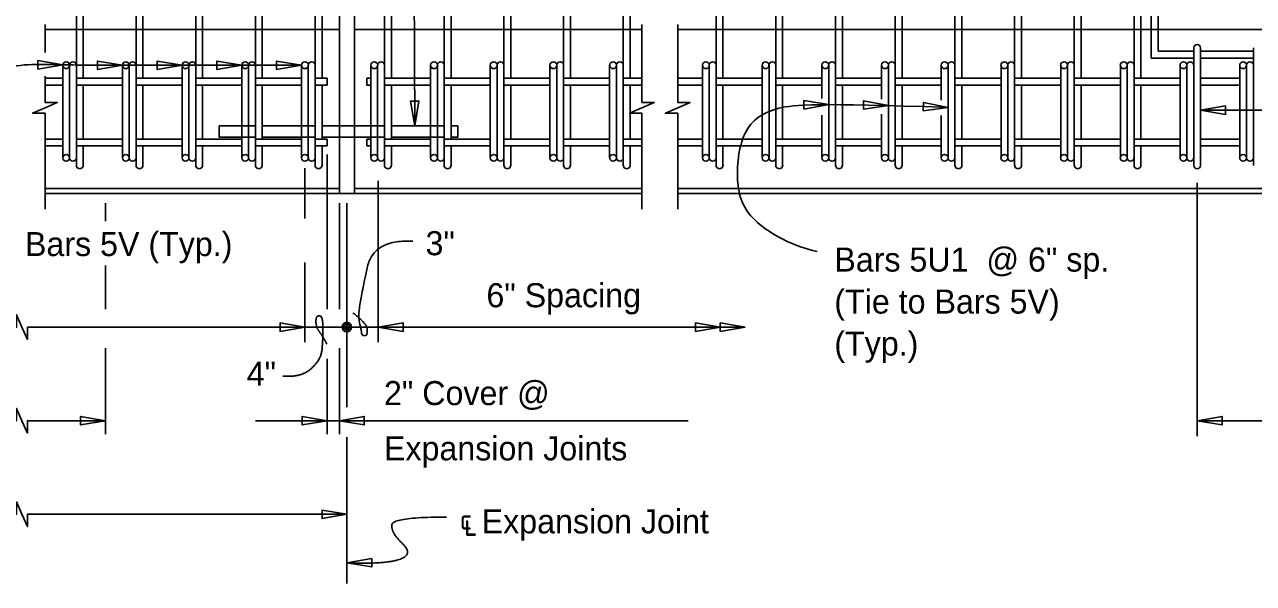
# Model space of a CAD drawing. Extents: x 120577.8 to 120649.9, y 120677.2 to 120721.6.
# Drawn here: x 120592.76 to 120603.05, y 120703.74 to 120708.42 of the extents above; entities that cross this region are included whole.
import ezdxf

# ---------------------------------------------------------------- set-up
doc = ezdxf.new("R2010")
doc.units = 0
for name, color, linetype in [('AdhocPoint_dp', 7, 'Continuous'), ('Border', 7, 'Continuous'), ('Patterning', 7, 'Continuous'), ('PlotBorder_dp', 7, 'Continuous'), ('TextMisc', 7, 'Continuous')]:
    doc.layers.add(name, color=color, linetype=linetype)

msp = doc.modelspace()

# ---------------------------------------------------------------- linework, layer by layer
at = {"layer": 'AdhocPoint_dp'}
msp.add_line((120595.397, 120707.007), (120595.522, 120707.007), dxfattribs=at)
at = {"layer": 'Border'}
for p, q in [((120595.459, 120705.219), (120595.459, 120706.927)), ((120595.459, 120703.741), (120595.459, 120704.966))]:
    msp.add_line(p, q, dxfattribs=at)
at = {"layer": 'Patterning'}
for p, q in [((120593.194, 120707.244), (120593.194, 120713.861)), ((120593.251, 120713.861), (120593.251, 120707.974)), ((120594.194, 120707.244), (120594.194, 120713.861)), ((120594.251, 120713.861), (120594.251, 120707.974)), ((120594.694, 120707.244), (120594.694, 120713.861)), ((120594.751, 120713.861), (120594.751, 120707.974)), ((120595.194, 120707.244), (120595.194, 120713.861)), ((120595.251, 120713.861), (120595.251, 120707.974)), ((120595.774, 120707.244), (120595.774, 120713.861)), ((120595.832, 120713.861), (120595.832, 120707.974)), ((120596.274, 120707.244), (120596.274, 120713.861)), ((120596.332, 120713.861), (120596.332, 120707.974)), ((120596.774, 120707.244), (120596.774, 120713.861)), ((120596.832, 120713.861), (120596.832, 120707.974)), ((120597.274, 120707.244), (120597.274, 120713.861)), ((120597.332, 120713.861), (120597.332, 120707.974)), ((120597.774, 120707.244), (120597.774, 120713.861)), ((120597.832, 120713.861), (120597.832, 120707.974)), ((120598.552, 120707.244), (120598.552, 120713.861)), ((120598.609, 120713.861), (120598.609, 120707.974)), ((120599.052, 120707.244), (120599.052, 120713.861)), ((120599.109, 120713.861), (120599.109, 120707.974)), ((120599.552, 120707.244), (120599.552, 120713.861)), ((120599.609, 120713.861), (120599.609, 120707.974)), ((120600.052, 120707.244), (120600.052, 120713.861)), ((120600.109, 120713.861), (120600.109, 120707.974)), ((120600.552, 120707.244), (120600.552, 120713.861)), ((120600.609, 120713.861), (120600.609, 120707.974)), ((120601.052, 120707.244), (120601.052, 120713.861)), ((120601.109, 120713.861), (120601.109, 120707.974)), ((120601.552, 120707.244), (120601.552, 120713.861)), ((120601.609, 120713.861), (120601.609, 120707.974)), ((120602.052, 120707.244), (120602.052, 120713.861)), ((120602.109, 120713.861), (120602.109, 120707.974)), ((120593.694, 120707.244), (120593.694, 120712.988)), ((120593.751, 120713.013), (120593.751, 120707.974)), ((120602.197, 120708.749), (120602.197, 120708.143)), ((120602.255, 120708.749), (120602.255, 120708.2)), ((120602.255, 120708.2), (120602.552, 120708.2)), ((120602.552, 120707.244), (120602.552, 120708.229)), ((120602.609, 120708.229), (120602.609, 120707.244)), ((120603.052, 120707.244), (120603.052, 120708.229)), ((120593.079, 120708.083), (120593.079, 120707.307)), ((120593.136, 120707.974), (120593.136, 120708.083)), ((120593.136, 120708.083), (120593.136, 120707.387)), ((120593.579, 120708.083), (120593.579, 120707.307)), ((120593.636, 120707.974), (120593.636, 120708.083)), ((120593.636, 120708.083), (120593.636, 120707.387)), ((120594.079, 120708.083), (120594.079, 120707.307)), ((120594.136, 120707.974), (120594.136, 120708.083)), ((120594.136, 120708.083), (120594.136, 120707.387)), ((120594.579, 120708.083), (120594.579, 120707.307)), ((120594.636, 120707.974), (120594.636, 120708.083)), ((120594.636, 120708.083), (120594.636, 120707.387)), ((120595.079, 120708.083), (120595.079, 120707.307)), ((120595.136, 120707.974), (120595.136, 120708.083)), ((120595.136, 120708.083), (120595.136, 120707.387)), ((120595.66, 120708.083), (120595.66, 120707.307)), ((120595.717, 120707.974), (120595.717, 120708.083)), ((120595.717, 120708.083), (120595.717, 120707.387)), ((120596.16, 120708.083), (120596.16, 120707.307)), ((120596.217, 120707.974), (120596.217, 120708.083)), ((120596.217, 120708.083), (120596.217, 120707.387)), ((120596.66, 120708.083), (120596.66, 120707.307)), ((120596.717, 120707.974), (120596.717, 120708.083)), ((120596.717, 120708.083), (120596.717, 120707.387)), ((120597.16, 120708.083), (120597.16, 120707.307)), ((120597.217, 120707.974), (120597.217, 120708.083)), ((120597.217, 120708.083), (120597.217, 120707.387)), ((120597.66, 120708.083), (120597.66, 120707.307)), ((120597.717, 120707.974), (120597.717, 120708.083)), ((120597.717, 120708.083), (120597.717, 120707.387)), ((120598.438, 120708.083), (120598.438, 120707.307)), ((120598.495, 120707.974), (120598.495, 120708.083)), ((120598.495, 120708.083), (120598.495, 120707.387)), ((120598.938, 120708.083), (120598.938, 120707.307)), ((120598.995, 120707.974), (120598.995, 120708.083)), ((120598.995, 120708.083), (120598.995, 120707.387)), ((120599.438, 120708.083), (120599.438, 120707.803)), ((120599.495, 120707.974), (120599.495, 120708.083)), ((120599.495, 120708.083), (120599.495, 120707.387)), ((120599.938, 120708.083), (120599.938, 120707.798)), ((120599.995, 120707.974), (120599.995, 120708.083)), ((120599.995, 120708.083), (120599.995, 120707.387)), ((120600.438, 120708.083), (120600.438, 120707.79)), ((120600.495, 120707.974), (120600.495, 120708.083)), ((120600.495, 120708.083), (120600.495, 120707.387)), ((120600.938, 120708.083), (120600.938, 120707.307)), ((120600.995, 120707.974), (120600.995, 120708.083)), ((120600.995, 120708.083), (120600.995, 120707.387)), ((120601.438, 120708.083), (120601.438, 120707.307)), ((120601.495, 120707.974), (120601.495, 120708.083)), ((120601.495, 120708.083), (120601.495, 120707.387)), ((120601.938, 120708.083), (120601.938, 120707.307)), ((120601.995, 120707.974), (120601.995, 120708.083)), ((120601.995, 120708.083), (120601.995, 120707.387)), ((120602.438, 120708.083), (120602.438, 120707.307)), ((120602.495, 120707.974), (120602.495, 120708.083)), ((120602.495, 120708.083), (120602.495, 120707.387)), ((120602.938, 120708.083), (120602.938, 120707.307)), ((120602.995, 120707.974), (120602.995, 120708.083)), ((120602.995, 120708.083), (120602.995, 120707.387)), ((120595.293, 120707.974), (120595.293, 120707.917)), ((120595.626, 120707.974), (120595.626, 120707.917)), ((120598.438, 120707.974), (120598.231, 120707.974)), ((120598.938, 120707.974), (120598.552, 120707.974)), ((120599.438, 120707.974), (120599.052, 120707.974)), ((120599.938, 120707.974), (120599.552, 120707.974)), ((120600.438, 120707.974), (120600.052, 120707.974)), ((120600.938, 120707.974), (120600.552, 120707.974)), ((120601.438, 120707.974), (120601.052, 120707.974)), ((120601.938, 120707.974), (120601.552, 120707.974)), ((120602.438, 120707.974), (120602.052, 120707.974)), ((120602.938, 120707.974), (120602.609, 120707.974)), ((120593.136, 120707.464), (120593.136, 120707.917)), ((120593.251, 120707.917), (120593.251, 120707.464)), ((120593.636, 120707.464), (120593.636, 120707.917)), ((120593.751, 120707.917), (120593.751, 120707.464)), ((120594.136, 120707.464), (120594.136, 120707.917)), ((120594.251, 120707.917), (120594.251, 120707.464)), ((120594.636, 120707.464), (120594.636, 120707.917)), ((120594.751, 120707.917), (120594.751, 120707.464)), ((120595.136, 120707.464), (120595.136, 120707.917)), ((120595.251, 120707.917), (120595.251, 120707.464)), ((120595.717, 120707.464), (120595.717, 120707.917)), ((120595.832, 120707.917), (120595.832, 120707.464)), ((120596.217, 120707.464), (120596.217, 120707.917)), ((120596.332, 120707.917), (120596.332, 120707.464)), ((120596.717, 120707.464), (120596.717, 120707.917)), ((120596.832, 120707.917), (120596.832, 120707.464)), ((120597.217, 120707.464), (120597.217, 120707.917)), ((120597.332, 120707.917), (120597.332, 120707.464)), ((120597.717, 120707.464), (120597.717, 120707.917)), ((120597.832, 120707.917), (120597.832, 120707.464)), ((120598.438, 120707.917), (120598.231, 120707.917)), ((120598.495, 120707.464), (120598.495, 120707.917)), ((120598.938, 120707.917), (120598.552, 120707.917)), ((120598.609, 120707.917), (120598.609, 120707.464)), ((120598.995, 120707.464), (120598.995, 120707.917)), ((120599.438, 120707.917), (120599.052, 120707.917)), ((120599.109, 120707.917), (120599.109, 120707.464)), ((120599.495, 120707.464), (120599.495, 120707.917)), ((120599.938, 120707.917), (120599.552, 120707.917)), ((120599.609, 120707.917), (120599.609, 120707.464)), ((120599.995, 120707.464), (120599.995, 120707.917)), ((120600.438, 120707.917), (120600.052, 120707.917)), ((120600.109, 120707.917), (120600.109, 120707.464)), ((120600.495, 120707.464), (120600.495, 120707.917)), ((120600.938, 120707.917), (120600.552, 120707.917)), ((120600.609, 120707.917), (120600.609, 120707.464)), ((120600.995, 120707.464), (120600.995, 120707.917)), ((120601.438, 120707.917), (120601.052, 120707.917)), ((120601.109, 120707.917), (120601.109, 120707.464)), ((120601.495, 120707.464), (120601.495, 120707.917)), ((120601.938, 120707.917), (120601.552, 120707.917)), ((120601.609, 120707.917), (120601.609, 120707.464)), ((120601.995, 120707.464), (120601.995, 120707.917)), ((120602.438, 120707.917), (120602.052, 120707.917)), ((120602.109, 120707.917), (120602.109, 120707.464)), ((120602.495, 120707.464), (120602.495, 120707.917)), ((120602.938, 120707.917), (120602.609, 120707.917)), ((120602.995, 120707.464), (120602.995, 120707.917)), ((120599.438, 120707.666), (120599.438, 120707.307)), ((120599.938, 120707.674), (120599.938, 120707.307)), ((120600.438, 120707.663), (120600.438, 120707.307)), ((120595.293, 120707.464), (120595.293, 120707.407)), ((120595.626, 120707.464), (120595.626, 120707.407)), ((120598.438, 120707.464), (120598.231, 120707.464)), ((120598.938, 120707.464), (120598.552, 120707.464)), ((120599.438, 120707.464), (120599.052, 120707.464)), ((120599.938, 120707.464), (120599.552, 120707.464)), ((120600.438, 120707.464), (120600.052, 120707.464)), ((120600.938, 120707.464), (120600.552, 120707.464)), ((120601.438, 120707.464), (120601.052, 120707.464)), ((120601.938, 120707.464), (120601.552, 120707.464)), ((120602.438, 120707.464), (120602.052, 120707.464)), ((120602.938, 120707.464), (120602.609, 120707.464)), ((120593.136, 120707.307), (120593.136, 120707.407)), ((120593.251, 120707.407), (120593.251, 120707.244)), ((120593.636, 120707.307), (120593.636, 120707.407)), ((120593.751, 120707.407), (120593.751, 120707.244)), ((120594.136, 120707.307), (120594.136, 120707.407)), ((120594.251, 120707.407), (120594.251, 120707.244)), ((120594.636, 120707.307), (120594.636, 120707.407)), ((120594.751, 120707.407), (120594.751, 120707.244)), ((120595.136, 120707.307), (120595.136, 120707.407)), ((120595.251, 120707.407), (120595.251, 120707.244)), ((120595.717, 120707.307), (120595.717, 120707.407)), ((120595.832, 120707.407), (120595.832, 120707.244)), ((120596.217, 120707.307), (120596.217, 120707.407)), ((120596.332, 120707.407), (120596.332, 120707.244)), ((120596.717, 120707.307), (120596.717, 120707.407)), ((120596.832, 120707.407), (120596.832, 120707.244)), ((120597.217, 120707.307), (120597.217, 120707.407)), ((120597.332, 120707.407), (120597.332, 120707.244)), ((120597.717, 120707.307), (120597.717, 120707.407)), ((120597.832, 120707.407), (120597.832, 120707.244)), ((120598.438, 120707.407), (120598.231, 120707.407)), ((120598.495, 120707.307), (120598.495, 120707.407)), ((120598.938, 120707.407), (120598.552, 120707.407)), ((120598.609, 120707.407), (120598.609, 120707.244)), ((120598.995, 120707.307), (120598.995, 120707.407)), ((120599.438, 120707.407), (120599.052, 120707.407)), ((120599.109, 120707.407), (120599.109, 120707.244)), ((120599.495, 120707.307), (120599.495, 120707.407)), ((120599.938, 120707.407), (120599.552, 120707.407)), ((120599.609, 120707.407), (120599.609, 120707.244)), ((120599.995, 120707.307), (120599.995, 120707.407)), ((120600.438, 120707.407), (120600.052, 120707.407)), ((120600.109, 120707.407), (120600.109, 120707.244)), ((120600.495, 120707.307), (120600.495, 120707.407)), ((120600.938, 120707.407), (120600.552, 120707.407)), ((120600.609, 120707.407), (120600.609, 120707.244)), ((120600.995, 120707.307), (120600.995, 120707.407)), ((120601.438, 120707.407), (120601.052, 120707.407)), ((120601.109, 120707.407), (120601.109, 120707.244)), ((120601.495, 120707.307), (120601.495, 120707.407)), ((120601.938, 120707.407), (120601.552, 120707.407)), ((120601.609, 120707.407), (120601.609, 120707.244)), ((120601.995, 120707.307), (120601.995, 120707.407)), ((120602.438, 120707.407), (120602.052, 120707.407)), ((120602.109, 120707.407), (120602.109, 120707.244)), ((120602.495, 120707.307), (120602.495, 120707.407)), ((120602.938, 120707.407), (120602.609, 120707.407)), ((120602.995, 120707.307), (120602.995, 120707.407))]:
    msp.add_line(p, q, dxfattribs=at)
for points in [[(120602.197, 120708.143), (120602.552, 120708.143)], [(120603.052, 120708.2), (120602.609, 120708.2)], [(120602.609, 120708.143), (120603.052, 120708.143)], [(120593.079, 120707.974), (120592.931, 120707.974)], [(120593.579, 120707.974), (120593.194, 120707.974)], [(120594.079, 120707.974), (120593.694, 120707.974)], [(120594.579, 120707.974), (120594.194, 120707.974)], [(120595.079, 120707.974), (120594.694, 120707.974)], [(120595.293, 120707.974), (120595.194, 120707.974)], [(120595.66, 120707.974), (120595.626, 120707.974)], [(120596.16, 120707.974), (120595.774, 120707.974)], [(120596.66, 120707.974), (120596.274, 120707.974)], [(120597.16, 120707.974), (120596.774, 120707.974)], [(120597.66, 120707.974), (120597.274, 120707.974)], [(120597.931, 120707.974), (120597.774, 120707.974)], [(120592.931, 120707.917), (120593.079, 120707.917)], [(120593.194, 120707.917), (120593.579, 120707.917)], [(120593.694, 120707.917), (120594.079, 120707.917)], [(120594.194, 120707.917), (120594.579, 120707.917)], [(120594.694, 120707.917), (120595.079, 120707.917)], [(120595.194, 120707.917), (120595.293, 120707.917)], [(120595.626, 120707.917), (120595.66, 120707.917)], [(120595.774, 120707.917), (120596.16, 120707.917)], [(120596.274, 120707.917), (120596.66, 120707.917)], [(120596.774, 120707.917), (120597.16, 120707.917)], [(120597.274, 120707.917), (120597.66, 120707.917)], [(120597.774, 120707.917), (120597.931, 120707.917)], [(120594.389, 120707.575), (120594.694, 120707.575)], [(120594.694, 120707.481), (120594.389, 120707.481), (120594.389, 120707.575)], [(120594.751, 120707.575), (120595.194, 120707.575)], [(120595.251, 120707.575), (120595.774, 120707.575)], [(120595.832, 120707.575), (120596.274, 120707.575)], [(120596.332, 120707.575), (120596.389, 120707.575), (120596.389, 120707.481), (120596.332, 120707.481)], [(120593.079, 120707.464), (120592.931, 120707.464)], [(120593.579, 120707.464), (120593.194, 120707.464)], [(120594.079, 120707.464), (120593.694, 120707.464)], [(120594.579, 120707.464), (120594.194, 120707.464)], [(120595.079, 120707.464), (120594.694, 120707.464)], [(120595.194, 120707.481), (120594.751, 120707.481)], [(120595.293, 120707.464), (120595.194, 120707.464)], [(120595.774, 120707.481), (120595.251, 120707.481)], [(120595.66, 120707.464), (120595.626, 120707.464)], [(120596.16, 120707.464), (120595.774, 120707.464)], [(120596.274, 120707.481), (120595.832, 120707.481)], [(120596.66, 120707.464), (120596.274, 120707.464)], [(120597.16, 120707.464), (120596.774, 120707.464)], [(120597.66, 120707.464), (120597.274, 120707.464)], [(120597.931, 120707.464), (120597.774, 120707.464)], [(120592.931, 120707.407), (120593.079, 120707.407)], [(120593.194, 120707.407), (120593.579, 120707.407)], [(120593.694, 120707.407), (120594.079, 120707.407)], [(120594.194, 120707.407), (120594.579, 120707.407)], [(120594.694, 120707.407), (120595.079, 120707.407)], [(120595.194, 120707.407), (120595.293, 120707.407)], [(120595.626, 120707.407), (120595.66, 120707.407)], [(120595.774, 120707.407), (120596.16, 120707.407)], [(120596.274, 120707.407), (120596.66, 120707.407)], [(120596.774, 120707.407), (120597.16, 120707.407)], [(120597.274, 120707.407), (120597.66, 120707.407)], [(120597.774, 120707.407), (120597.931, 120707.407)]]:
    msp.add_lwpolyline(points, dxfattribs=at)
for centre in [(120593.108, 120708.083), (120593.608, 120708.083), (120594.108, 120708.083), (120594.608, 120708.083), (120595.108, 120708.083), (120595.689, 120708.083), (120596.189, 120708.083), (120596.689, 120708.083), (120597.189, 120708.083), (120597.689, 120708.083), (120598.466, 120708.083), (120598.966, 120708.083), (120599.466, 120708.083), (120599.966, 120708.083), (120600.466, 120708.083), (120600.966, 120708.083), (120601.466, 120708.083), (120601.966, 120708.083), (120602.466, 120708.083), (120602.966, 120708.083), (120593.108, 120707.307), (120593.608, 120707.307), (120594.108, 120707.307), (120594.608, 120707.307), (120595.108, 120707.307), (120595.689, 120707.307), (120596.189, 120707.307), (120596.689, 120707.307), (120597.189, 120707.307), (120597.689, 120707.307), (120598.466, 120707.307), (120598.966, 120707.307), (120599.466, 120707.307), (120599.966, 120707.307), (120600.466, 120707.307), (120600.966, 120707.307), (120601.466, 120707.307), (120601.966, 120707.307), (120602.466, 120707.307), (120602.966, 120707.307)]:
    msp.add_circle(centre, 0.0286, dxfattribs=at)
for centre, start, end in [((120602.581, 120708.229), 0, 180), ((120593.165, 120708.083), 0, 180), ((120593.665, 120708.083), 0, 180), ((120594.165, 120708.083), 0, 180), ((120594.665, 120708.083), 0, 180), ((120595.165, 120708.083), 0, 180), ((120595.746, 120708.083), 0, 180), ((120596.246, 120708.083), 0, 180), ((120596.746, 120708.083), 0, 180), ((120597.246, 120708.083), 0, 180), ((120597.746, 120708.083), 0, 180), ((120598.523, 120708.083), 0, 180), ((120599.023, 120708.083), 0, 180), ((120599.523, 120708.083), 0, 180), ((120600.023, 120708.083), 0, 180), ((120600.523, 120708.083), 0, 180), ((120601.023, 120708.083), 0, 180), ((120601.523, 120708.083), 0, 180), ((120602.023, 120708.083), 0, 180), ((120602.523, 120708.083), 0, 180), ((120603.023, 120708.083), 0, 180), ((120593.165, 120707.307), 180, 0), ((120593.222, 120707.244), 179.0229, 0.9771), ((120593.665, 120707.307), 180, 0), ((120593.722, 120707.244), 179.0229, 0.9771), ((120594.165, 120707.307), 180, 0), ((120594.222, 120707.244), 179.0229, 0.9771), ((120594.665, 120707.307), 180, 0), ((120594.722, 120707.244), 179.0229, 0.9771), ((120595.165, 120707.307), 180, 0), ((120595.222, 120707.244), 179.0229, 0.9771), ((120595.746, 120707.307), 180, 0), ((120595.803, 120707.244), 179.0229, 0.9771), ((120596.246, 120707.307), 180, 0), ((120596.303, 120707.244), 179.0229, 0.9771), ((120596.746, 120707.307), 180, 0), ((120596.803, 120707.244), 179.0229, 0.9771), ((120597.246, 120707.307), 180, 0), ((120597.303, 120707.244), 179.0229, 0.9771), ((120597.746, 120707.307), 180, 0), ((120597.803, 120707.244), 179.0229, 0.9771), ((120598.523, 120707.307), 180, 0), ((120598.581, 120707.244), 179.0229, 0.9771), ((120599.023, 120707.307), 180, 0), ((120599.081, 120707.244), 179.0229, 0.9771), ((120599.523, 120707.307), 180, 0), ((120599.581, 120707.244), 179.0229, 0.9771), ((120600.023, 120707.307), 180, 0), ((120600.081, 120707.244), 179.0229, 0.9771), ((120600.523, 120707.307), 180, 0), ((120600.581, 120707.244), 179.0229, 0.9771), ((120601.023, 120707.307), 180, 0), ((120601.081, 120707.244), 179.0229, 0.9771), ((120601.523, 120707.307), 180, 0), ((120601.581, 120707.244), 179.0229, 0.9771), ((120602.023, 120707.307), 180, 0), ((120602.081, 120707.244), 179.0229, 0.9771), ((120602.523, 120707.307), 180, 0), ((120602.581, 120707.244), 180, 0), ((120603.023, 120707.307), 180, 0)]:
    msp.add_arc(centre, 0.0286, start, end, dxfattribs=at)
at = {"layer": 'PlotBorder_dp'}
for p, q in [((120595.293, 120707.334), (120595.293, 120706.039)), ((120595.108, 120707.221), (120595.108, 120706.8)), ((120595.722, 120707.115), (120595.722, 120705.763)), ((120602.581, 120704.974), (120602.581, 120707.099)), ((120593.437, 120706.927), (120593.437, 120706.776)), ((120595.397, 120706.927), (120595.397, 120706.039)), ((120593.437, 120706.406), (120593.437, 120706.039)), ((120595.108, 120706.429), (120595.108, 120705.763)), ((120593.437, 120705.711), (120593.437, 120704.991)), ((120595.397, 120705.711), (120595.397, 120704.991)), ((120595.293, 120705.624), (120595.293, 120704.991)), ((120598.319, 120705.104), (120594.694, 120705.104)), ((120607.581, 120705.104), (120602.581, 120705.104))]:
    msp.add_line(p, q, dxfattribs=at)
for points in [[(120592.931, 120708.189), (120592.931, 120708.424)], [(120597.931, 120706.878), (120597.931, 120707.681), (120597.827, 120707.681), (120597.931, 120707.726), (120598.034, 120707.771), (120597.931, 120707.771), (120597.931, 120708.424)], [(120598.231, 120706.878), (120598.231, 120707.681), (120598.127, 120707.681), (120598.231, 120707.726), (120598.334, 120707.771), (120598.231, 120707.771), (120598.231, 120708.424)], [(120592.931, 120706.878), (120592.931, 120707.681), (120592.827, 120707.681), (120592.931, 120707.726), (120593.034, 120707.771), (120592.931, 120707.771), (120592.931, 120707.991)], [(120582.277, 120705.888), (120592.693, 120705.888), (120592.693, 120705.992), (120592.738, 120705.888), (120592.783, 120705.785), (120592.783, 120705.888), (120598.794, 120705.888)], [(120585.364, 120705.104), (120592.693, 120705.104), (120592.693, 120705.208), (120592.738, 120705.104), (120592.783, 120705.001), (120592.783, 120705.104), (120593.437, 120705.104)], [(120585.364, 120704.32), (120592.693, 120704.32), (120592.693, 120704.424), (120592.738, 120704.32), (120592.783, 120704.217), (120592.783, 120704.32), (120595.459, 120704.32)]]:
    msp.add_lwpolyline(points, dxfattribs=at)
for points in [[(120593.079, 120708.086), (120592.871, 120708.122), (120592.871, 120708.051)], [(120593.579, 120708.083), (120593.371, 120708.118), (120593.371, 120708.047)], [(120594.079, 120708.083), (120593.871, 120708.118), (120593.871, 120708.047)], [(120594.579, 120708.083), (120594.371, 120708.118), (120594.371, 120708.047)], [(120595.079, 120708.083), (120594.871, 120708.118), (120594.871, 120708.047)], [(120596.029, 120707.575), (120596.063, 120707.783), (120595.992, 120707.783)], [(120599.495, 120707.754), (120599.286, 120707.787), (120599.287, 120707.716)], [(120599.995, 120707.745), (120599.787, 120707.786), (120599.786, 120707.715)], [(120600.495, 120707.73), (120600.288, 120707.772), (120600.285, 120707.702)], [(120602.609, 120707.707), (120602.818, 120707.671), (120602.818, 120707.742)], [(120595.108, 120705.888), (120594.9, 120705.924), (120594.9, 120705.853)], [(120595.722, 120705.888), (120595.931, 120705.853), (120595.931, 120705.924)], [(120598.586, 120705.888), (120598.378, 120705.924), (120598.378, 120705.853)], [(120598.794, 120705.888), (120598.586, 120705.924), (120598.586, 120705.853)], [(120593.437, 120705.104), (120593.229, 120705.14), (120593.229, 120705.069)], [(120595.293, 120705.104), (120595.084, 120705.14), (120595.084, 120705.069)], [(120595.397, 120705.104), (120595.605, 120705.069), (120595.605, 120705.14)], [(120602.581, 120705.104), (120602.789, 120705.069), (120602.789, 120705.14)], [(120595.459, 120704.32), (120595.251, 120704.356), (120595.251, 120704.285)], [(120595.459, 120703.914), (120595.668, 120703.879), (120595.668, 120703.949)]]:
    msp.add_lwpolyline(points, close=True, dxfattribs=at)
for radius in [0.0399, 0.0262, 0.0118]:
    msp.add_circle((120595.459, 120705.889), radius, dxfattribs=at)
for points, degree in [([(120596.531, 120714.934), (120596.193, 120714.972), (120596.07, 120714.566), (120595.999, 120714.193), (120596.029, 120707.575)], 3), ([(120592.647, 120706.631), (120592.565, 120706.651), (120592.442, 120706.749), (120592.368, 120707.12), (120592.368, 120707.736), (120592.482, 120708.107), (120593.079, 120708.083), (120593.579, 120708.083), (120594.079, 120708.083), (120594.579, 120708.083), (120595.079, 120708.083)], 3), ([(120599.397, 120706.523), (120599.197, 120706.566), (120598.826, 120706.766), (120598.705, 120707.064), (120598.757, 120707.568), (120599.034, 120707.747), (120599.388, 120707.766), (120600.495, 120707.73)], 3), ([(120608.663, 120706.461), (120608.223, 120706.427), (120608.299, 120706.882), (120608.29, 120706.854), (120608.403, 120707.673), (120607.92, 120707.707), (120607.359, 120707.696), (120602.609, 120707.707)], 2), ([(120596.013, 120706.609), (120595.68, 120706.626), (120595.578, 120706.146), (120595.553, 120705.972), (120595.583, 120705.854), (120595.583, 120705.817), (120595.628, 120705.817), (120595.628, 120705.856), (120595.628, 120705.911), (120595.51, 120706.009)], 2), ([(120594.922, 120705.478), (120595.077, 120705.466), (120595.241, 120705.613), (120595.259, 120705.774), (120595.259, 120705.984), (120595.2, 120705.984), (120595.2, 120705.888), (120595.256, 120705.815), (120595.291, 120705.747)], 2), ([(120596.294, 120704.297), (120595.848, 120704.297), (120595.825, 120704.17), (120596.021, 120703.983), (120595.778, 120703.901), (120595.459, 120703.914)], 2)]:
    msp.add_open_spline(points, degree=degree, dxfattribs=at)
at = {"layer": 'TextMisc'}
for p, q in [((120595.397, 120714.028), (120595.397, 120707.007)), ((120595.522, 120714.028), (120595.522, 120707.007)), ((120595.397, 120708.382), (120592.931, 120708.382)), ((120597.931, 120708.382), (120595.522, 120708.382)), ((120611.931, 120708.382), (120598.231, 120708.382)), ((120595.397, 120707.049), (120592.931, 120707.049)), ((120597.931, 120707.049), (120595.522, 120707.049)), ((120611.931, 120707.049), (120598.231, 120707.049)), ((120595.397, 120707.007), (120592.931, 120707.007)), ((120597.931, 120707.007), (120595.522, 120707.007)), ((120611.931, 120707.007), (120598.231, 120707.007))]:
    msp.add_line(p, q, dxfattribs=at)

# ---------------------------------------------------------------- texts
at = {"layer": 'AdhocPoint_dp'}
for s, p in [('Bars 5V (Typ.)', (120592.763, 120706.484)), ('3"', (120596.118, 120706.491)), ('6" Spacing', (120596.628, 120706.055)), ('4"', (120594.62, 120705.397)), ('2" Cover @', (120595.77, 120705.235)), ('Expansion Joints', (120595.77, 120704.772)), ('℄ Expansion Joint', (120596.404, 120704.16))]:
    msp.add_text(s, height=0.2016, dxfattribs=at).set_placement(p)
at = {"layer": 'PlotBorder_dp'}
for s, p in [('Bars 5U1  @ 6" sp.', (120599.542, 120706.354)), ('(Tie to Bars 5V)', (120599.542, 120706.002)), ('(Typ.)', (120599.542, 120705.65))]:
    msp.add_text(s, height=0.2016, dxfattribs=at).set_placement(p)

doc.saveas('drawing.dxf')
